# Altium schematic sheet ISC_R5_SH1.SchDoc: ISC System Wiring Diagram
size B; DrawnBy: Filiberto Clara; Engineer: Filiberto Clara; Organization: LIGO Laboratory; Address1: California Institute of Technology; Address2: Massachusetts Institute of Technology; SheetNumber: 19; SheetTotal: 39
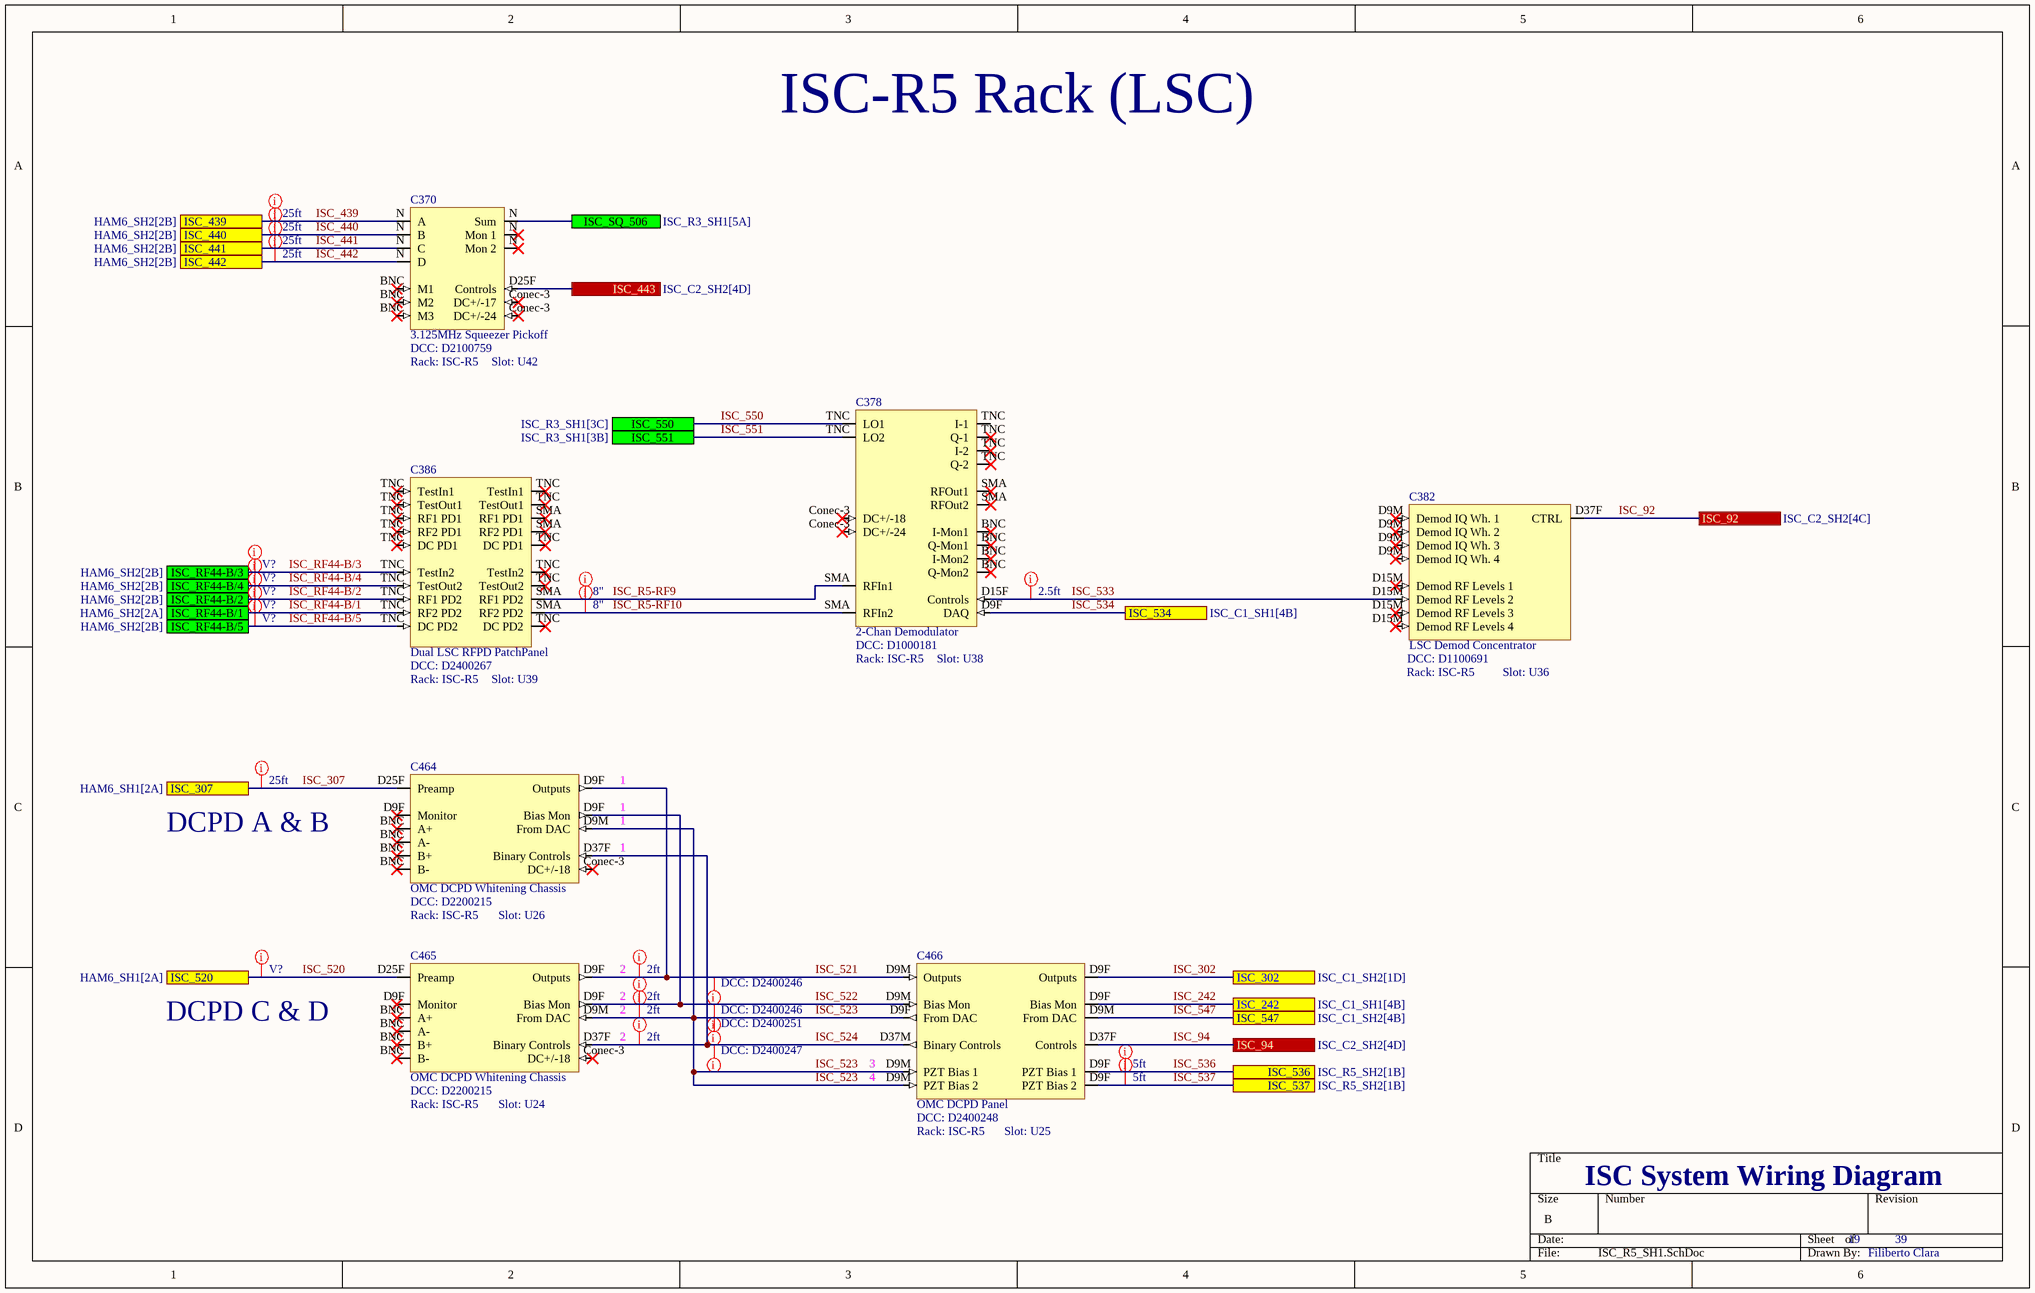
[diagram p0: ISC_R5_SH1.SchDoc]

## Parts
C370  3.125MHz Squeezer Pickoff  DCC: D2100759  Rack: ISC-R5  Slot: U42
C378  2-Chan Demodulator  DCC: D1000181  Rack: ISC-R5  Slot: U38
C382  LSC Demod Concentrator  DCC: D1100691  Rack: ISC-R5  Slot: U36
C386  Dual LSC RFPD PatchPanel  DCC: D2400267  Rack: ISC-R5  Slot: U39
C464  OMC DCPD Whitening Chassis  DCC: D2200215  Rack: ISC-R5  Slot: U26
C465  OMC DCPD Whitening Chassis  DCC: D2200215  Rack: ISC-R5  Slot: U24
C466  OMC DCPD Panel  DCC: D2400248  Rack: ISC-R5  Slot: U25

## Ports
ISC_92 (see ISC_C2_SH2[4C]), ISC_94 (see ISC_C2_SH2[4D]), ISC_242 (see ISC_C1_SH1[4B]), ISC_302 (see ISC_C1_SH2[1D]), ISC_307 (see HAM6_SH1[2A]), ISC_439 (see HAM6_SH2[2B]), ISC_440 (see HAM6_SH2[2B]), ISC_441 (see HAM6_SH2[2B]), ISC_442 (see HAM6_SH2[2B]), ISC_443 (see ISC_C2_SH2[4D]), ISC_520 (see HAM6_SH1[2A]), ISC_534 (see ISC_C1_SH1[4B]), ISC_536 (see ISC_R5_SH2[1B]), ISC_537 (see ISC_R5_SH2[1B]), ISC_547 (see ISC_C1_SH2[4B]), ISC_550 (see ISC_R3_SH1[3C]), ISC_551 (see ISC_R3_SH1[3B]), ISC_RF44-B/1 (see HAM6_SH2[2A]), ISC_RF44-B/2 (see HAM6_SH2[2B]), ISC_RF44-B/3 (see HAM6_SH2[2B]), ISC_RF44-B/4 (see HAM6_SH2[2B]), ISC_RF44-B/5 (see HAM6_SH2[2B]), ISC_SQ_506 (see ISC_R3_SH1[5A])

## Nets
ISC_92: C382.D37F(CTRL) ; port ISC_92
ISC_94: C466.D37F(Controls) ; port ISC_94
ISC_242: C466.D9F(Bias_Mon) ; port ISC_242
ISC_302: C466.D9F(Outputs) ; port ISC_302
ISC_307: C464.D25F(Preamp) ; port ISC_307
ISC_439: C370.N(A) ; port ISC_439
ISC_440: C370.N(B) ; port ISC_440
ISC_441: C370.N(C) ; port ISC_441
ISC_442: C370.N(D) ; port ISC_442
ISC_443: C370.D25F(Controls) ; port ISC_443
ISC_520: C465.D25F(Preamp) ; port ISC_520
ISC_521: C464.D9F(Outputs) C465.D9F(Outputs) C466.D9M(Outputs)
ISC_522: C464.D9F(Bias_Mon) C465.D9F(Bias_Mon) C466.D9M(Bias_Mon)
ISC_523: C464.D9M(From_DAC) C465.D9M(From_DAC) C466.D9F(From_DAC) C466.D9M(PZT_Bias_1)
ISC_524: C464.D37F(Binary_Controls) C465.D37F(Binary_Controls) C466.D37M(Binary_Controls)
ISC_533: C378.D15F(Controls) C382.D15M(Demod_RF_Levels_1)
ISC_534: C378.D9F(DAQ) ; port ISC_534
ISC_536: C466.D9F(PZT_Bias_1) ; port ISC_536
ISC_537: C466.D9F(PZT_Bias_2) ; port ISC_537
ISC_547: C466.D9M(From_DAC) ; port ISC_547
ISC_550: C378.TNC(LO1) ; port ISC_550
ISC_551: C378.TNC(LO2) ; port ISC_551
ISC_R5-RF9: C378.SMA(RFOut1) C386.SMA(RF1_PD1)
ISC_R5-RF10: C378.SMA(RFIn2) C386.SMA(RF2_PD2)
ISC_RF44-B/1: C386.TNC(RF2_PD2) ; port ISC_RF44-B/1
ISC_RF44-B/2: C386.TNC(RF1_PD2) ; port ISC_RF44-B/2
ISC_RF44-B/3: C386.TNC(TestIn1) ; port ISC_RF44-B/3
ISC_RF44-B/4: C386.TNC(TestOut2) ; port ISC_RF44-B/4
ISC_RF44-B/5: C386.TNC(DC_PD2) ; port ISC_RF44-B/5
ISC_SQ_506: C370.N(Sum) ; port ISC_SQ_506

Not connected (* = marked no-connect by the designer): C370 BNC(M1)* Conec-3(DC+/-17)*; C378 BNC(I-Mon1)* Conec-3(DC+/-18)*; C382 D9M(Demod_IQ_Wh._1)*; C464 BNC(A+)* Conec-3(DC+/-18)*; C465 BNC(A+)* Conec-3(DC+/-18)*

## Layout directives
Length: 25ft: ISC_307, ISC_439, ISC_440, ISC_441, ISC_442
Length: 8": ISC_R5-RF9, ISC_R5-RF10
Length: 2.5ft: ISC_533
Length: V?: ISC_520, ISC_RF44-B/1, ISC_RF44-B/2, ISC_RF44-B/3, ISC_RF44-B/4, ISC_RF44-B/5
Length: 2ft: ISC_521, ISC_522, ISC_523, ISC_524
DCC: D2400247: ISC_524
DCC: D2400251: ISC_523
DCC: D2400246: ISC_521, ISC_522
Length: 5ft: ISC_536, ISC_537

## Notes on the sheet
- ISC-R5 Rack (LSC)
- DCPD A & B
- (near C464) 1
- (near C465) 2
- DCPD C & D
- (near C466) 3
- (near C466) 4

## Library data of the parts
C370 = 3.125MHz Squeezer Pickoff: Serial: Sxxxxxxx; System: ISC
C378 = 2-Chan Demod: Serial: Sxxxxxxx; System: ISC
C382 = LSC Demod Concentrator: Serial: Sxxxxxxx; System: ISC
C386 = LSC RFPD PatchPanel Dual: Serial: Sxxxxxxx; System: ISC
C464 C465 = OMC DCPD Whitening Chassis: Serial: Sxxxxxxx; System: ISC
C466 = OMC DCPD Panel: Serial: Sxxxxxxx; System: ISC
